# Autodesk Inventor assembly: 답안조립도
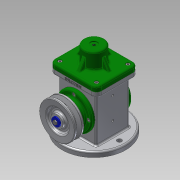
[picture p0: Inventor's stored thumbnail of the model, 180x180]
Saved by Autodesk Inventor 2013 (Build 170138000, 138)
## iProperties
Created: 2018-10
Part Number: 답안조립도
Document SubType Name: Assembly
Designer: Administrator
Author: Administrator
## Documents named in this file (18)
- C:\Users\Administrator\Desktop\481007V1050\답안조립도.iam
- C:\Users\Administrator\Desktop\481007V1050\본체.ipt
- C:\Users\Administrator\Desktop\481007V1050\E-링.ipt
- C:\Users\Administrator\Desktop\481007V1050\V-벨트풀리.ipt
- C:\Users\Administrator\Desktop\481007V1050\덮개.ipt
- C:\Users\Administrator\Desktop\481007V1050\뒤커버.ipt
- C:\Users\Administrator\Desktop\481007V1050\링크.ipt
- C:\Users\Administrator\Desktop\481007V1050\베어링 17 x 40 x 12.ipt
- C:\Users\Administrator\Desktop\481007V1050\볼트 M4 x 8.ipt
- C:\Users\Administrator\Desktop\481007V1050\볼트 M4 x 10.ipt
- C:\Users\Administrator\Desktop\481007V1050\슬라이더.ipt
- C:\Users\Administrator\Desktop\481007V1050\앞커버.ipt
- C:\Users\Administrator\Desktop\481007V1050\오일 실 17 30 8.ipt
- C:\Users\Administrator\Desktop\481007V1050\와셔 4x16.ipt
- C:\Users\Administrator\Desktop\481007V1050\클레비스 핀 6 x 22.ipt
- 클레비스 핀 6 x 22.ipt
- C:\Users\Administrator\Desktop\481007V1050\키 4 x 4 x 12.ipt
- C:\Users\Administrator\Desktop\481007V1050\편심축.ipt
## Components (2 placed, 2 different names)
1. E-링:1
2. V-벨트풀리:1
